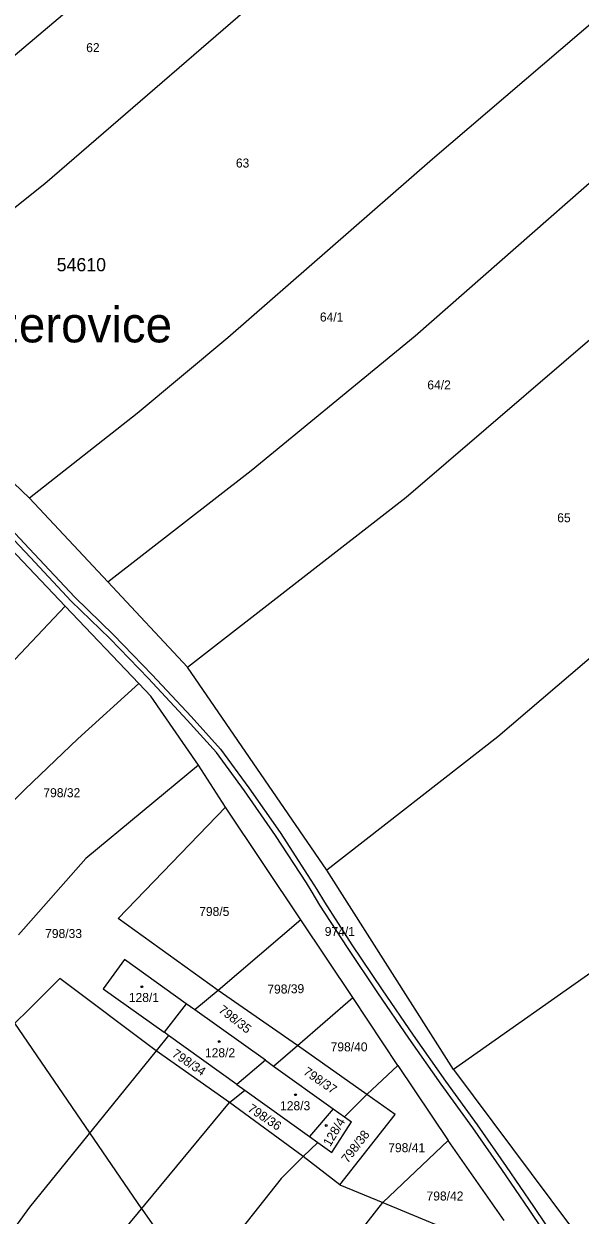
# Model space of a CAD drawing. Extents: x -749173 to -746119, y -1132678 to -1130338.
# Drawn here: x -747694.7 to -747589.9, y -1131323.7 to -1131098.8 of the extents above; entities that cross this region are included whole.
import ezdxf

# ---------------------------------------------------------------- set-up
doc = ezdxf.new("R2010")
doc.units = 0
for name, color, linetype in [('Vrstva 1', 7, 'Continuous'), ('Vrstva 15', 7, 'Continuous'), ('Vrstva 18', 7, 'Continuous'), ('Vrstva 19', 7, 'Continuous'), ('Vrstva 25', 7, 'Continuous'), ('Vrstva 3', 7, 'Continuous'), ('Vrstva 30', 7, 'Continuous'), ('Vrstva 37', 7, 'Continuous'), ('Vrstva 52', 7, 'Continuous'), ('Vrstva 53', 7, 'Continuous'), ('Vrstva 6', 7, 'Continuous')]:
    doc.layers.add(name, color=color, linetype=linetype)

msp = doc.modelspace()

# ---------------------------------------------------------------- linework, layer by layer
at = {"layer": 'Vrstva 1'}
for points in [[(-747702.08, -1131109.45), (-747662.38, -1131075.87)], [(-747705.95, -1131176.64), (-747693.71, -1131188.35)], [(-747678.94, -1131204.15), (-747693.71, -1131188.35)], [(-747686.96, -1131208.76), (-747699.59, -1131195.48)], [(-747663.87, -1131220.26), (-747678.94, -1131204.15)], [(-747673.07, -1131223.37), (-747686.96, -1131208.76)], [(-747637.6, -1131258.56), (-747663.87, -1131220.26)], [(-747670.79, -1131225.76), (-747673.07, -1131223.37)], [(-747661.79, -1131238.73), (-747670.79, -1131225.76)], [(-747656.71, -1131246.65), (-747661.79, -1131238.73)], [(-747656.71, -1131246.65), (-747676.97, -1131267.67)], [(-747642.55, -1131267.96), (-747656.71, -1131246.65)], [(-747613.72, -1131296.16), (-747637.6, -1131258.56)], [(-747658.09, -1131281.3), (-747676.97, -1131267.67)], [(-747632.73, -1131282.6), (-747642.55, -1131267.96)], [(-747675.77, -1131275.42), (-747679.79, -1131280.94)], [(-747664.12, -1131283.77), (-747675.77, -1131275.42)], [(-747702.43, -1131293.35), (-747687.96, -1131278.99)], [(-747669.82, -1131292.66), (-747687.96, -1131278.99)], [(-747679.79, -1131280.94), (-747668.32, -1131289.17)], [(-747643.16, -1131291.66), (-747658.09, -1131281.3)], [(-747624.26, -1131295.45), (-747632.73, -1131282.6)], [(-747664.12, -1131283.77), (-747668.32, -1131289.17)], [(-747662.52, -1131284.92), (-747664.12, -1131283.77)], [(-747649.2, -1131294.46), (-747662.52, -1131284.92)], [(-747667.48, -1131289.77), (-747668.32, -1131289.17)], [(-747654.61, -1131299), (-747667.48, -1131289.77)], [(-747630.05, -1131300.93), (-747643.16, -1131291.66)], [(-747656, -1131302.39), (-747669.82, -1131292.66)], [(-747649.2, -1131294.46), (-747654.61, -1131299)], [(-747649.2, -1131294.46), (-747647.65, -1131295.57)], [(-747647.65, -1131295.57), (-747636.4, -1131303.63)], [(-747624.26, -1131295.45), (-747614.76, -1131309.6)], [(-747613.72, -1131296.16), (-747587.97, -1131330.74)], [(-747654.61, -1131299), (-747653.1, -1131300.08)], [(-747653.1, -1131300.08), (-747640.91, -1131308.82)], [(-747624.72, -1131304.69), (-747630.05, -1131300.93)], [(-747642.09, -1131312.59), (-747656, -1131302.39)], [(-747636.4, -1131303.63), (-747640.91, -1131308.82)], [(-747636.4, -1131303.63), (-747634.28, -1131305.15)], [(-747635.14, -1131317.96), (-747624.72, -1131304.69)], [(-747634.28, -1131305.15), (-747632.97, -1131306.09)], [(-747636.7, -1131311.84), (-747632.97, -1131306.09)], [(-747640.91, -1131308.82), (-747639.3, -1131309.98)], [(-747639.3, -1131309.98), (-747636.7, -1131311.84)], [(-747604.21, -1131324.68), (-747614.76, -1131309.6)], [(-747635.14, -1131317.96), (-747642.09, -1131312.59)], [(-747635.14, -1131317.96), (-747627.04, -1131321.32)], [(-747627.04, -1131321.32), (-747608.88, -1131328.87)]]:
    msp.add_lwpolyline(points, dxfattribs=at)
at = {"layer": 'Vrstva 25'}
for centre in [(-747672.48, -1131280.56), (-747657.9, -1131290.93), (-747643.53, -1131300.95), (-747637.72, -1131306.77)]:
    msp.add_circle(centre, 0.175, dxfattribs=at)
at = {"layer": 'Vrstva 3'}
for points in [[(-747675.77, -1131275.42), (-747679.79, -1131280.94)], [(-747664.12, -1131283.77), (-747675.77, -1131275.42)], [(-747679.79, -1131280.94), (-747668.32, -1131289.17)], [(-747662.52, -1131284.92), (-747664.12, -1131283.77)], [(-747649.2, -1131294.46), (-747662.52, -1131284.92)], [(-747667.48, -1131289.77), (-747668.32, -1131289.17)], [(-747654.61, -1131299), (-747667.48, -1131289.77)], [(-747649.2, -1131294.46), (-747647.65, -1131295.57)], [(-747647.65, -1131295.57), (-747636.4, -1131303.63)], [(-747654.61, -1131299), (-747653.1, -1131300.08)], [(-747653.1, -1131300.08), (-747640.91, -1131308.82)], [(-747636.4, -1131303.63), (-747634.28, -1131305.15)], [(-747634.28, -1131305.15), (-747632.97, -1131306.09)], [(-747636.7, -1131311.84), (-747632.97, -1131306.09)], [(-747640.91, -1131308.82), (-747639.3, -1131309.98)], [(-747639.3, -1131309.98), (-747636.7, -1131311.84)]]:
    msp.add_lwpolyline(points, dxfattribs=at)
at = {"layer": 'Vrstva 30'}
for points in [[(-747700.12, -1131191.14), (-747692.78, -1131198.87)], [(-747693.52, -1131199.55), (-747700.84, -1131191.84)], [(-747685.83, -1131207.77), (-747693.52, -1131199.55)], [(-747692.78, -1131198.87), (-747685.11, -1131207.07)], [(-747678.54, -1131214.85), (-747685.83, -1131207.77)], [(-747685.11, -1131207.07), (-747677.84, -1131214.15)], [(-747671.27, -1131222.4), (-747678.54, -1131214.85)], [(-747677.84, -1131214.15), (-747670.55, -1131221.72)], [(-747663.96, -1131230.23), (-747671.27, -1131222.4)], [(-747670.55, -1131221.72), (-747663.22, -1131229.57)], [(-747658.43, -1131236.38), (-747663.96, -1131230.23)], [(-747663.22, -1131229.57), (-747657.65, -1131235.75)], [(-747657.65, -1131235.75), (-747652.34, -1131243.04)], [(-747653.14, -1131243.62), (-747658.43, -1131236.38)], [(-747647.27, -1131252.05), (-747653.14, -1131243.62)], [(-747652.34, -1131243.04), (-747646.44, -1131251.49)], [(-747646.44, -1131251.49), (-747640.61, -1131260.45)], [(-747641.45, -1131260.99), (-747647.27, -1131252.05)], [(-747640.61, -1131260.45), (-747639.53, -1131262.22)], [(-747640.39, -1131262.74), (-747641.45, -1131260.99)], [(-747638.92, -1131265.16), (-747640.39, -1131262.74)], [(-747639.53, -1131262.22), (-747638.08, -1131264.64)], [(-747633.72, -1131273.19), (-747638.92, -1131265.16)], [(-747638.08, -1131264.64), (-747632.88, -1131272.64)], [(-747627.98, -1131281.7), (-747633.72, -1131273.19)], [(-747632.88, -1131272.64), (-747627.16, -1131281.14)], [(-747622.16, -1131290.27), (-747627.98, -1131281.7)], [(-747627.16, -1131281.14), (-747621.34, -1131289.71)], [(-747621.34, -1131289.71), (-747615.24, -1131298.37)], [(-747616.06, -1131298.95), (-747622.16, -1131290.27)], [(-747610.11, -1131307.22), (-747616.06, -1131298.95)], [(-747615.24, -1131298.37), (-747609.29, -1131306.64)], [(-747604.63, -1131315.09), (-747610.11, -1131307.22)], [(-747609.29, -1131306.64), (-747603.81, -1131314.53)], [(-747603.81, -1131314.53), (-747598.64, -1131322.03)], [(-747599.47, -1131322.59), (-747604.63, -1131315.09)], [(-747594.17, -1131330.47), (-747599.47, -1131322.59)], [(-747598.64, -1131322.03), (-747593.87, -1131329.15)]]:
    msp.add_lwpolyline(points, dxfattribs=at)
at = {"layer": 'Vrstva 37'}
msp.add_circle((-747657.9, -1131290.93), 0.175, dxfattribs=at)
at = {"layer": 'Vrstva 52'}
msp.add_lwpolyline([(-747851.21, -1131174.25), (-747826.21, -1131184.4), (-747815.66, -1131188.68), (-747811.5, -1131190.37), (-747782.68, -1131206.28), (-747767.97, -1131214.41), (-747766, -1131215.5), (-747752.69, -1131224.86), (-747752.45, -1131225.03), (-747745.56, -1131229.87), (-747738.24, -1131236.78), (-747731.12, -1131243.5), (-747725.56, -1131249.91), (-747716.69, -1131260.12), (-747714.03, -1131263.42), (-747706.44, -1131272.87), (-747704.9, -1131275.12), (-747702.48, -1131278.66), (-747696.48, -1131287.44), (-747682.34, -1131308.14), (-747672.55, -1131322.46), (-747672.44, -1131322.62), (-747663.5, -1131335.37)], dxfattribs=at)
at = {"layer": 'Vrstva 6'}
for points in [[(-747690.81, -1131128.96), (-747643.31, -1131087.92)], [(-747583.1, -1131094.79), (-747617.7, -1131124.35)], [(-747620.97, -1131157.74), (-747567.13, -1131110.4)], [(-747617.7, -1131124.35), (-747656.27, -1131158.12)], [(-747726.24, -1131157.28), (-747690.81, -1131128.96)], [(-747622.68, -1131188.16), (-747577.82, -1131149.69)], [(-747656.27, -1131158.12), (-747673.39, -1131172.41)], [(-747651.91, -1131183.16), (-747620.97, -1131157.74)], [(-747673.39, -1131172.41), (-747693.71, -1131188.35)], [(-747678.94, -1131204.15), (-747651.91, -1131183.16)], [(-747663.87, -1131220.26), (-747622.68, -1131188.16)], [(-747686.96, -1131208.76), (-747710.17, -1131233.27)], [(-747586.04, -1131216.89), (-747605.36, -1131233.4)], [(-747684.57, -1131233.76), (-747673.07, -1131223.37)], [(-747694.48, -1131243.3), (-747684.57, -1131233.76)], [(-747605.36, -1131233.4), (-747637.6, -1131258.56)], [(-747661.79, -1131238.73), (-747683.08, -1131256.39)], [(-747705.1, -1131253.98), (-747694.48, -1131243.3)], [(-747683.08, -1131256.39), (-747695.74, -1131270.78)], [(-747642.55, -1131267.96), (-747658.09, -1131281.3)], [(-747584.62, -1131275.69), (-747613.72, -1131296.16)], [(-747658.09, -1131281.3), (-747662.52, -1131284.92)], [(-747643.16, -1131291.66), (-747632.73, -1131282.6)], [(-747667.48, -1131289.77), (-747669.82, -1131292.66)], [(-747647.65, -1131295.57), (-747643.16, -1131291.66)], [(-747669.82, -1131292.66), (-747693.71, -1131322.2)], [(-747624.26, -1131295.45), (-747630.05, -1131300.93)], [(-747656, -1131302.39), (-747653.1, -1131300.08)], [(-747630.05, -1131300.93), (-747634.28, -1131305.15)], [(-747681.87, -1131333.76), (-747656, -1131302.39)], [(-747639.3, -1131309.98), (-747642.09, -1131312.59)], [(-747627.04, -1131321.32), (-747614.76, -1131309.6)], [(-747642.09, -1131312.59), (-747646.2, -1131316.75)], [(-747646.2, -1131316.75), (-747664.28, -1131339.63)], [(-747669.96, -1131376.28), (-747627.04, -1131321.32)], [(-747693.71, -1131322.2), (-747729.49, -1131371.5)]]:
    msp.add_lwpolyline(points, dxfattribs=at)

# ---------------------------------------------------------------- texts
at = {"layer": 'Vrstva 15'}
msp.add_text('Bežerovice', height=6.7, dxfattribs=at).set_placement((-747711.12, -1131158.96))
at = {"layer": 'Vrstva 18'}
for s, p in [('62', (-747682.99, -1131104.18)), ('63', (-747654.77, -1131125.96)), ('64/1', (-747638.93, -1131155.02)), ('64/2', (-747618.67, -1131167.83)), ('65', (-747594.18, -1131192.91)), ('798/32', (-747691.06, -1131244.8)), ('798/5', (-747661.68, -1131267.22)), ('798/33', (-747690.73, -1131271.38)), ('974/1', (-747638.01, -1131270.99)), ('798/40', (-747636.9, -1131292.77)), ('798/41', (-747626.04, -1131311.8)), ('798/42', (-747618.82, -1131320.92))]:
    msp.add_text(s, height=1.7, dxfattribs=at).set_placement(p)
for s, rotation, p in [('798/39', 1.1111, (-747648.82, -1131281.91)), ('798/35', 322.1555, (-747658.18, -1131285.24)), ('798/34', 325.9228, (-747666.95, -1131293.6)), ('798/37', 325.5126, (-747642.2, -1131296.98)), ('798/36', 326.3099, (-747652.69, -1131303.95)), ('798/38', 52.4922, (-747633.68, -1131313.99))]:
    msp.add_text(s, height=1.7, rotation=rotation, dxfattribs=at).set_placement(p)
at = {"layer": 'Vrstva 19'}
for s, p in [('128/1', (-747674.95, -1131283.45)), ('128/2', (-747660.6, -1131293.88)), ('128/3', (-747646.44, -1131303.88))]:
    msp.add_text(s, height=1.7, dxfattribs=at).set_placement(p)
msp.add_text('128/4', height=1.7, rotation=59.2767, dxfattribs=at).set_placement((-747636.98, -1131310.86))
at = {"layer": 'Vrstva 53'}
msp.add_text('54610', height=2.5, dxfattribs=at).set_placement((-747688.55, -1131145.54))

doc.saveas('drawing.dxf')
